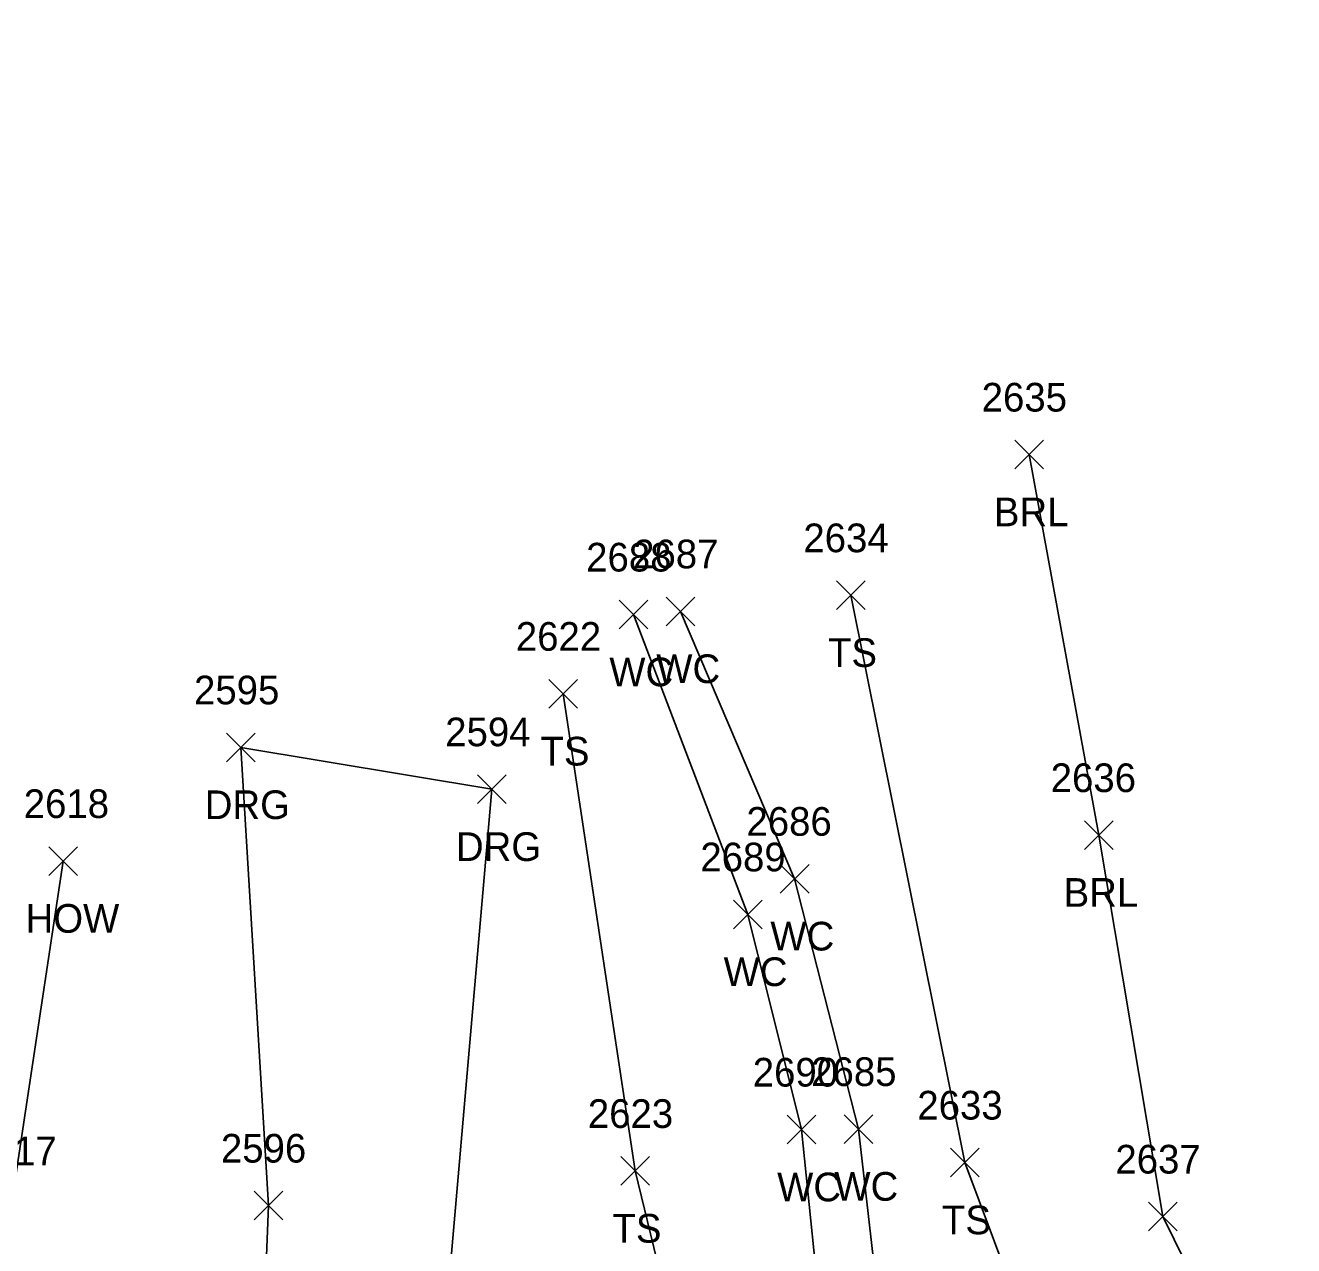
# Model space of a CAD drawing. Extents: x 1609623 to 1616187, y 756677 to 762826.
# Drawn here: x 1610400.4 to 1610488.8, y 762060.4 to 762145.4 of the extents above; entities that cross this region are included whole.
import ezdxf

# ---------------------------------------------------------------- set-up
doc = ezdxf.new("R2010")
doc.units = 0
for name, color, linetype in [('L_A', 7, 'Continuous'), ('L_I', 7, 'Continuous'), ('L_TIC', 7, 'Continuous'), ('LABL', 7, 'Continuous'), ('LAWE', 7, 'Continuous'), ('LBC', 7, 'Continuous'), ('LELB', 7, 'Continuous'), ('R_A', 7, 'Continuous'), ('R_I', 7, 'Continuous'), ('R_TIC', 7, 'Continuous'), ('RDG', 7, 'Continuous')]:
    doc.layers.add(name, color=color, linetype=linetype)

msp = doc.modelspace()

# ---------------------------------------------------------------- linework, layer by layer
at = {"layer": 'L_TIC'}
for points in [[(1610469.363, 762114.52), (1610471.363, 762116.52)], [(1610471.363, 762114.52), (1610469.363, 762116.52)], [(1610456.931, 762104.712), (1610458.931, 762106.712)], [(1610458.931, 762104.712), (1610456.931, 762106.712)], [(1610445.061, 762103.588), (1610447.061, 762105.588)], [(1610447.061, 762103.588), (1610445.061, 762105.588)], [(1610441.786, 762103.366), (1610443.786, 762105.366)], [(1610443.786, 762103.366), (1610441.786, 762105.366)], [(1610436.883, 762097.84), (1610438.883, 762099.84)], [(1610438.883, 762097.84), (1610436.883, 762099.84)], [(1610474.229, 762087.986), (1610476.229, 762089.986)], [(1610476.229, 762087.986), (1610474.229, 762089.986)], [(1610402.004, 762086.178), (1610404.004, 762088.178)], [(1610404.004, 762086.178), (1610402.004, 762088.178)], [(1610453.017, 762084.941), (1610455.017, 762086.941)], [(1610455.017, 762084.941), (1610453.017, 762086.941)], [(1610449.756, 762082.46), (1610451.756, 762084.46)], [(1610451.756, 762082.46), (1610449.756, 762084.46)], [(1610453.489, 762067.451), (1610455.489, 762069.451)], [(1610455.489, 762067.451), (1610453.489, 762069.451)], [(1610457.478, 762067.491), (1610459.478, 762069.491)], [(1610459.478, 762067.491), (1610457.478, 762069.491)], [(1610441.903, 762064.568), (1610443.903, 762066.568)], [(1610443.903, 762064.568), (1610441.903, 762066.568)], [(1610464.875, 762065.152), (1610466.875, 762067.152)], [(1610466.875, 762065.152), (1610464.875, 762067.152)], [(1610478.687, 762061.387), (1610480.687, 762063.387)], [(1610480.687, 762061.387), (1610478.687, 762063.387)]]:
    msp.add_lwpolyline(points, dxfattribs=at)
at = {"layer": 'LABL'}
msp.add_lwpolyline([(1610470.363, 762115.52), (1610475.229, 762088.986), (1610479.687, 762062.387), (1610486.022, 762049.51), (1610500.718, 762036.949), (1610516.407, 762053.543), (1610531.563, 762075.461), (1610545.003, 762093.74), (1610548.442, 762128.029), (1610522.892, 762138.758), (1610498.156, 762145.449)], dxfattribs=at)
at = {"layer": 'LAWE'}
for points in [[(1610442.83, 762001.363), (1610454.027, 762011.196), (1610462.188, 762036.041), (1610458.478, 762068.491), (1610454.017, 762085.941), (1610446.061, 762104.588)], [(1610442.786, 762104.366), (1610450.756, 762083.46), (1610454.489, 762068.451), (1610457.732, 762036.851), (1610450.323, 762014.386), (1610439.796, 762002.568)]]:
    msp.add_lwpolyline(points, dxfattribs=at)
at = {"layer": 'LBC'}
msp.add_lwpolyline([(1610362.881, 762092.965), (1610359.551, 762068.376), (1610399.356, 762062.956), (1610403.004, 762087.178)], dxfattribs=at)
at = {"layer": 'LELB'}
msp.add_lwpolyline([(1610437.883, 762098.84), (1610442.903, 762065.568), (1610448.068, 762044.275), (1610448.524, 762027.086), (1610437.66, 762008.716), (1610437.983, 762000.71), (1610443.301, 761999.212), (1610449.856, 762004.078), (1610458.946, 762011.412), (1610471.32, 762038.35), (1610470.026, 762055.092), (1610465.875, 762066.152), (1610457.931, 762105.712)], dxfattribs=at)
at = {"layer": 'R_TIC'}
for points in [[(1610414.396, 762094.104), (1610416.396, 762096.104)], [(1610416.396, 762094.104), (1610414.396, 762096.104)], [(1610431.912, 762091.182), (1610433.912, 762093.182)], [(1610433.912, 762091.182), (1610431.912, 762093.182)], [(1610416.327, 762062.151), (1610418.327, 762064.151)], [(1610418.327, 762062.151), (1610416.327, 762064.151)]]:
    msp.add_lwpolyline(points, dxfattribs=at)
at = {"layer": 'RDG'}
msp.add_lwpolyline([(1610441.737, 761998.519), (1610429.085, 762000.521), (1610425.267, 762017.554), (1610429.458, 762052.577), (1610432.912, 762092.182), (1610415.396, 762095.104), (1610417.327, 762063.151), (1610416.186, 762034.399), (1610413.216, 762016.697), (1610403.836, 762011.057)], dxfattribs=at)

# ---------------------------------------------------------------- texts
at = {"layer": 'L_A'}
for s, p in [('BRL', (1610467.907, 762110.52)), ('TS', (1610456.34, 762100.712)), ('WC', (1610441.093, 762099.366)), ('WC', (1610444.368, 762099.588)), ('TS', (1610436.292, 762093.84)), ('BRL', (1610472.772, 762083.986)), ('HOW', (1610400.39, 762082.178)), ('WC', (1610452.324, 762080.941)), ('WC', (1610449.063, 762078.46)), ('WC', (1610452.796, 762063.451)), ('WC', (1610456.785, 762063.491)), ('TS', (1610464.285, 762061.152)), ('TS', (1610441.313, 762060.568))]:
    msp.add_text(s, height=2, dxfattribs=at).set_placement(p)
at = {"layer": 'L_I'}
for s, p in [('2635', (1610467.056, 762118.52)), ('2634', (1610454.624, 762108.712)), ('2688', (1610439.479, 762107.366)), ('2687', (1610442.754, 762107.588)), ('2622', (1610434.576, 762101.84)), ('2636', (1610471.867, 762091.986)), ('2618', (1610400.264, 762090.178)), ('2686', (1610450.654, 762088.941)), ('2689', (1610447.441, 762086.46)), ('2690', (1610451.095, 762071.451)), ('2685', (1610455.17, 762071.491)), ('2633', (1610462.568, 762069.152)), ('2623', (1610439.596, 762068.568)), ('2617', (1610396.615, 762065.956)), ('2637', (1610476.38, 762065.387))]:
    msp.add_text(s, height=2, dxfattribs=at).set_placement(p)
at = {"layer": 'R_A'}
for p in [(1610412.884, 762090.104), (1610430.4, 762087.182)]:
    msp.add_text('DRG', height=2, dxfattribs=at).set_placement(p)
at = {"layer": 'R_I'}
for s, p in [('2595', (1610412.136, 762098.104)), ('2594', (1610429.652, 762095.182)), ('2596', (1610414.012, 762066.151))]:
    msp.add_text(s, height=2, dxfattribs=at).set_placement(p)

doc.saveas('drawing.dxf')
